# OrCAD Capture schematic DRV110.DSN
size A; title: DRV110 - Power saving solenoid controller with integrated supply regulation.; rev: 1.1; note: SLVSBA8 –MARCH 2012
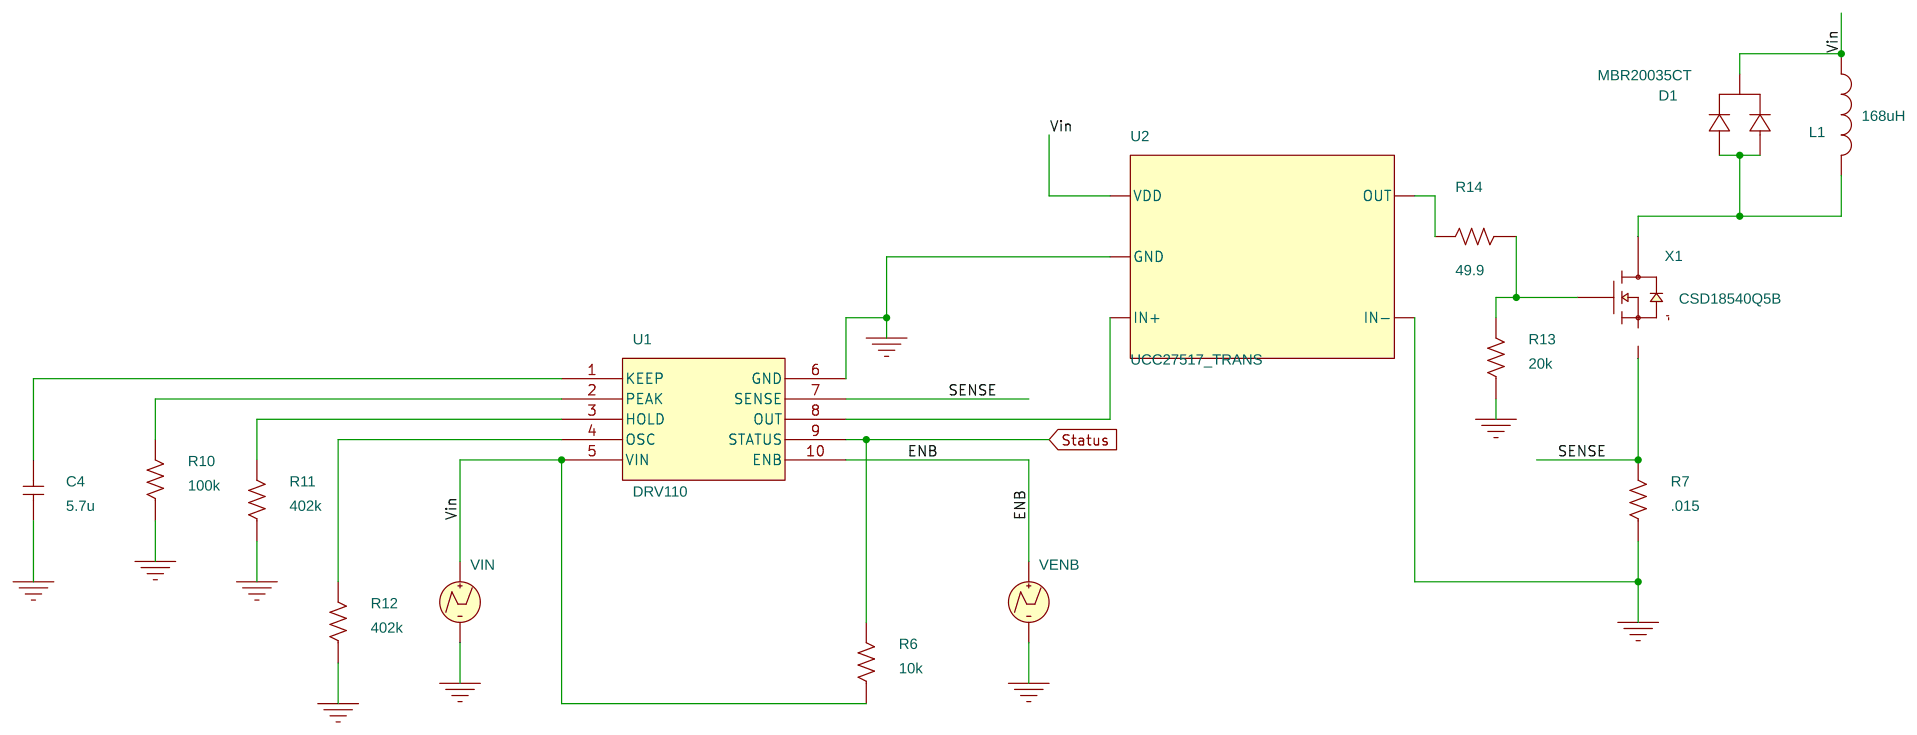
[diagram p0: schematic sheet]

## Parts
C4  5.7u  [RAD/CK05]
D1  MBR20035CT  [357C-03]
L1  168uH  [DISC/.350x.175/LS.200x.100/.034]
R6  10k  [AX/RC05]
R7  .015  [AX/RC05]
R10  100k  [AX/RC05]
R11  402k  [AX/RC05]
R12  402k  [AX/RC05]
R13  20k  [AX/RC05]
R14  49.9  [AX/RC05]
U1  DRV110
U2  UCC27517_TRANS
VENB  VPWL
VIN  VPWL
X1  CSD18540Q5B

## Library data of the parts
C4 = C
D1 = MBR20035CT
L1 = L: IC: 30A
R6 R7 R10-R14 = R
U1 = DRV110: PSpiceTemplate: X^@REFDES %KEEP %PEAK %HOLD %OSC %VIN %GND %SENSE %OUT %STATUS %ENB @MODEL
U2 = UCC27517_TRANS: PSpiceTemplate: X^@REFDES %IN+ %IN- %GND %OUT %VDD @MODEL
VENB = VPWL: PSpiceTemplate: V^@REFDES %+ %- ?DC|DC @DC| ?AC|AC @AC|\n+PWL @T1 @V1 @T2 @V2 #T3/@T3 @V3/ #T4/@T4 @V4/ #T5/@T5 @V5/ #T6/@T6 @V6/ #T7/@T7 @V7/ #T8/@T8 @V8/ #T9/@T9 @V9/ #T10/@T10 @V10/; T1: 0; T2: 1.200m; T3: 1.20001m; T4: 200m; T5: 200.00001m; V1: 0; V2: 0; V3: 3.3; V4: 3.3; V5: 0
VIN = VPWL: PSpiceTemplate: V^@REFDES %+ %- ?DC|DC @DC| ?AC|AC @AC|\n+PWL @T1 @V1 @T2 @V2 #T3/@T3 @V3/ #T4/@T4 @V4/ #T5/@T5 @V5/ #T6/@T6 @V6/ #T7/@T7 @V7/ #T8/@T8 @V8/ #T9/@T9 @V9/ #T10/@T10 @V10/; T1: 0; T2: 1.00m; V1: 0; V2: 12
X1 = CSD18540Q5B

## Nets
Vin: D1.3 L1.1 R6.1 U1.5(VIN) U2.VDD VIN.1(+)
0: C4.1 R7.1 R10.1 R11.1 R12.1 R13.1 U1.6(GND) U2.GND U2.IN- VENB.2(-) VIN.2(-)
ENB: U1.10(ENB) VENB.1(+)
SENSE: R7.2 U1.7(SENSE) X1.source
Status: R6.2 U1.9(STATUS)
N208566: R12.2 U1.4(OSC)
N208768: R11.2 U1.3(HOLD)
N208966: R10.2 U1.2(PEAK)
N209207: C4.2 U1.1(KEEP)
N14349652: D1.1 D1.2 L1.2 X1.drain
N14369286: U1.8(OUT) U2.IN+
N14370451: R14.2 U2.OUT
N14370458: R13.2 R14.1 X1.gate
